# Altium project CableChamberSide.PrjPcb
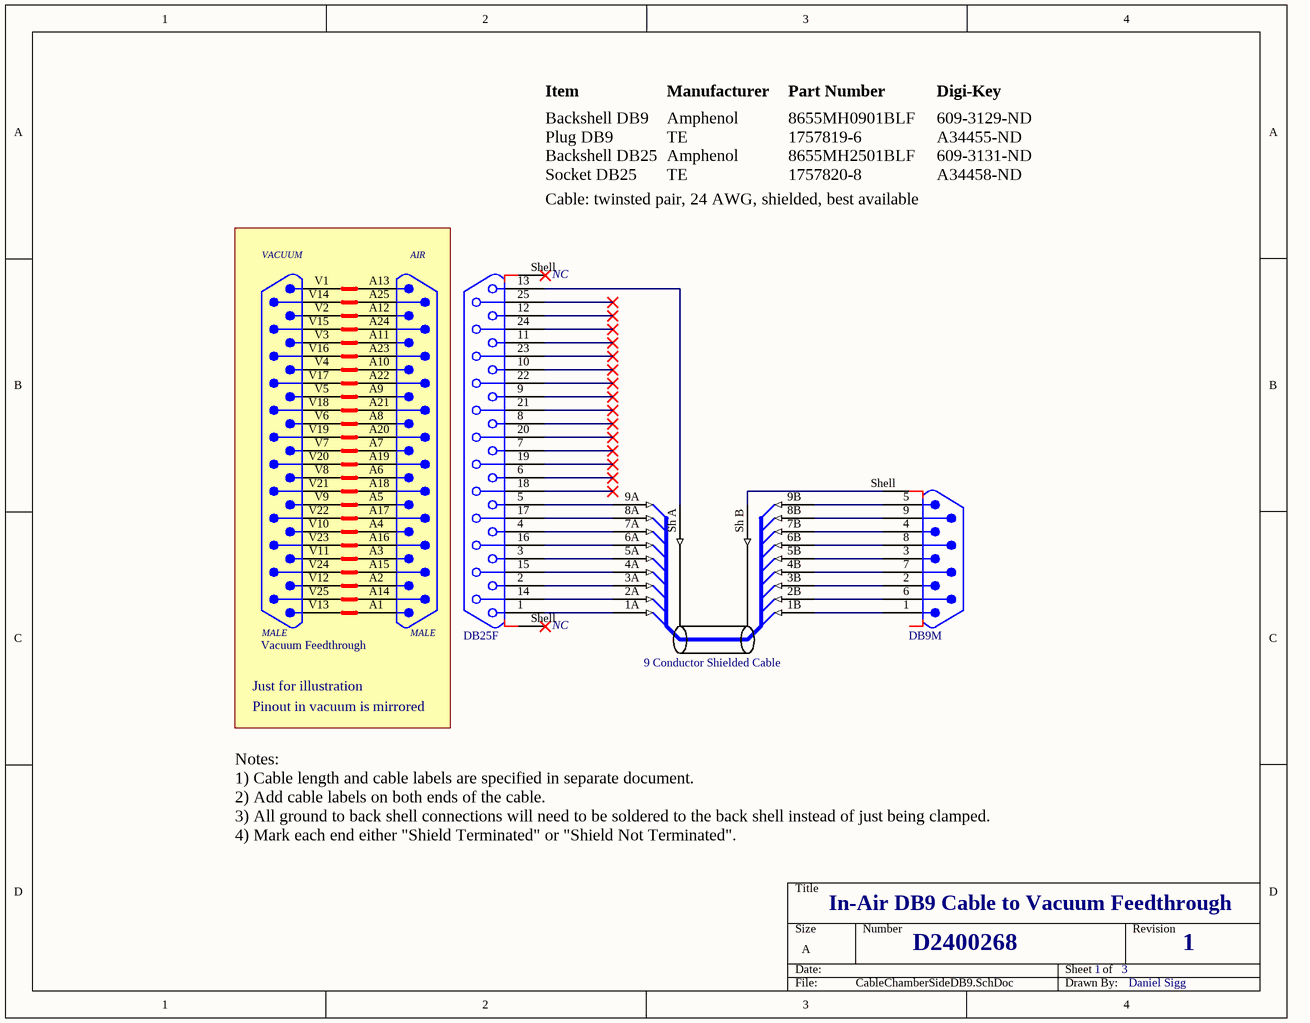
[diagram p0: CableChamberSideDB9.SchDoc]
Revision: 1; DCC: D2400268
3 sheets, 12 parts. Net scope: global (net labels, ports and power ports of the same name join across sheets).
Sheets:
  CableChamberSideDB9.SchDoc
  CableChamberSideDB15.SchDoc
  CableChamberSideDB25.SchDoc

## Sheet CableChamberSideDB9.SchDoc
size A; SheetNumber: 1; SheetTotal: 3

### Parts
Cable1  9 Conductor Shielded Cable
Feed1  Vacuum Feedthrough  (no BOM)
J1  DB25F
J2  DB9M  [DB9]

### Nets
NetCable1_1A: Cable1.1A J1.1
NetCable1_1B: Cable1.1B J2.1
NetCable1_2A: Cable1.2A J1.14
NetCable1_2B: Cable1.2B J2.6
NetCable1_3A: Cable1.3A J1.2
NetCable1_3B: Cable1.3B J2.2
NetCable1_4A: Cable1.4A J1.15
NetCable1_4B: Cable1.4B J2.7
NetCable1_5A: Cable1.5A J1.3
NetCable1_5B: Cable1.5B J2.3
NetCable1_6A: Cable1.6A J1.16
NetCable1_6B: Cable1.6B J2.8
NetCable1_7A: Cable1.7A J1.4
NetCable1_7B: Cable1.7B J2.4
NetCable1_8A: Cable1.8A J1.17
NetCable1_8B: Cable1.8B J2.9
NetCable1_9A: Cable1.9A J1.5
NetCable1_9B: Cable1.9B J2.5
NetCable1_Sh A: Cable1.Sh_A J1.13
NetCable1_Sh B: Cable1.Sh_B J2.Shell(SH1)

Not connected (* = marked no-connect by the designer): Feed1 A1 A2 A3 A4 A5 A6 A7 A8 A9 A10 A11 A12 A13 A14 A15 A16 A17 A18 A19 A20 A21 A22 A23 A24 A25 V1 V2 V3 V4 V5 V6 V7 V8 V9 V10 V11 V12 V13 V14 V15 V16 V17 V18 V19 V20 V21 V22 V23 V24 V25; J1 6* 7* 8* 9* 10* 11* 12* 18* 19* 20* 21* 22* 23* 24* 25* Shell*

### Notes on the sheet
- Item
- Manufacturer
- Part Number
- Digi-Key
- Backshell DB9
  Plug DB9
  Backshell DB25
  Socket DB25
- Cable: twinsted pair, 24 AWG, shielded, best available
- Amphenol
  TE
  Amphenol
  TE
- 8655MH0901BLF
  1757819-6
  8655MH2501BLF
  1757820-8
- 609-3129-ND
  A34455-ND
  609-3131-ND
  A34458-ND
- (near J1) NC
- Just for illustration
- Pinout in vacuum is mirrored
- Notes:
  1) Cable length and cable labels are specified in separate document.
  2) Add cable labels on both ends of the cable.
  3) All ground to back shell connections will need to be soldered to the back shell instead of just being clamped.
  4) Mark each end either "Shield Terminated" or "Shield Not Terminated".
- In-Air DB9 Cable to Vacuum Feedthrough
- Daniel Sigg

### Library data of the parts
Cable1 = Shielded 9 Cond: Connector A: 1757820-8; Connector B: 1757819-6
Feed1 = vac_feed_25p: Vacuum feedthrough 25-pin d-sub
J1 = D25-F-Shell: 25 Pin Female Cable End, D-Sub with Backshell
J2 = DB9M-Shell: 9 Pin Male Cable End, D-Sub with Backshell

## Sheet CableChamberSideDB15.SchDoc
size A; SheetNumber: 2; SheetTotal: 3
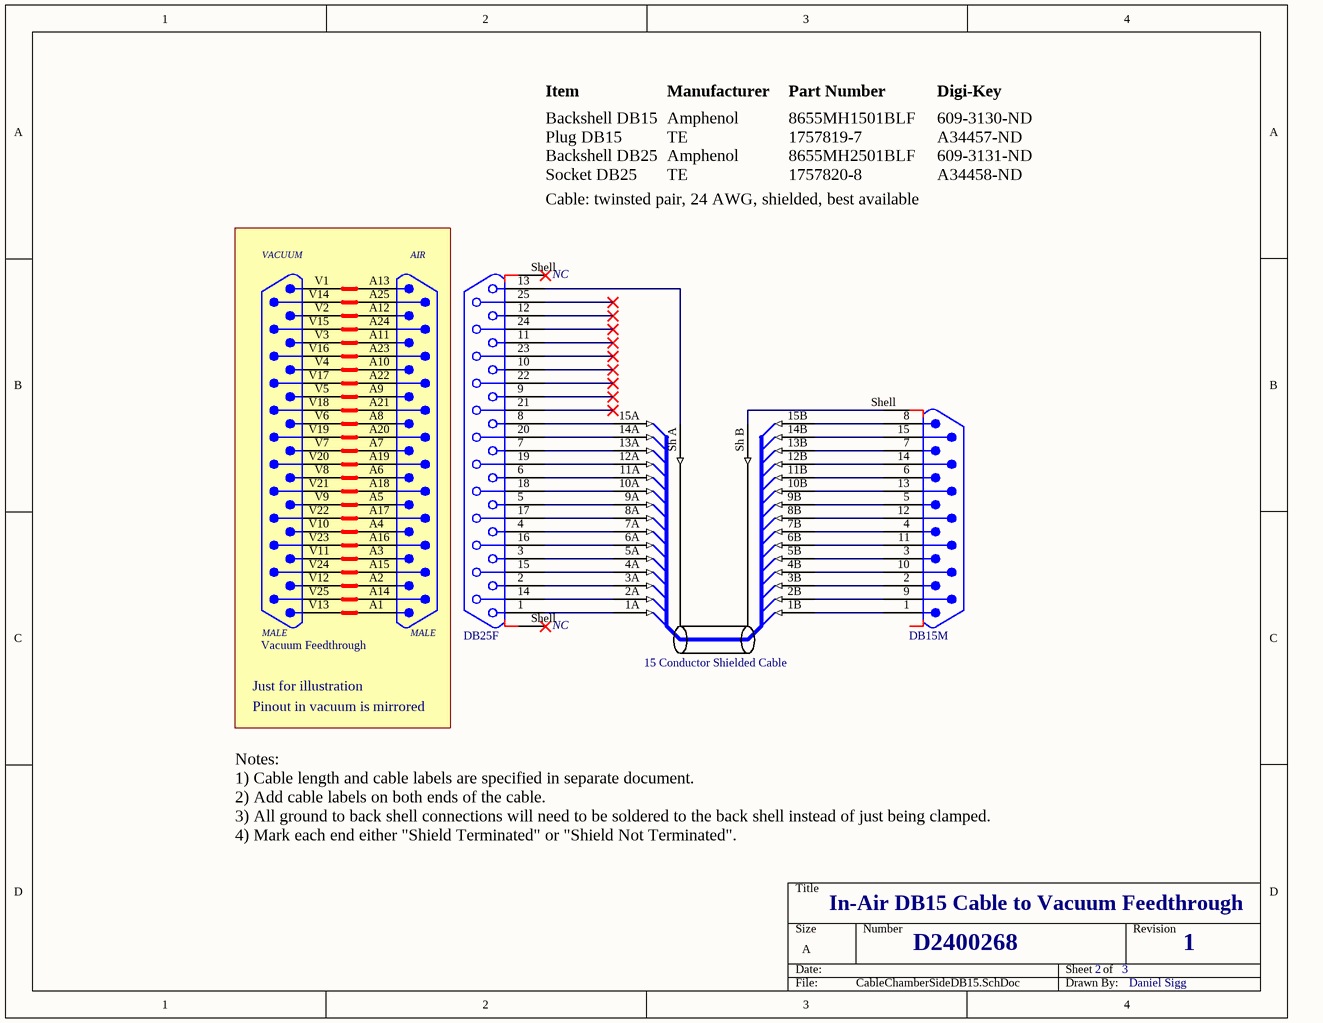
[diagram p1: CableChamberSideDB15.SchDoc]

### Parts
Cable2  15 Conductor Shielded Cable
Feed2  Vacuum Feedthrough  (no BOM)
J3  DB25F
J4  DB15M  [DB15]

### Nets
NetCable2_1A: Cable2.1A J3.1
NetCable2_1B: Cable2.1B J4.1
NetCable2_2A: Cable2.2A J3.14
NetCable2_2B: Cable2.2B J4.9
NetCable2_3A: Cable2.3A J3.2
NetCable2_3B: Cable2.3B J4.2
NetCable2_4A: Cable2.4A J3.15
NetCable2_4B: Cable2.4B J4.10
NetCable2_5A: Cable2.5A J3.3
NetCable2_5B: Cable2.5B J4.3
NetCable2_6A: Cable2.6A J3.16
NetCable2_6B: Cable2.6B J4.11
NetCable2_7A: Cable2.7A J3.4
NetCable2_7B: Cable2.7B J4.4
NetCable2_8A: Cable2.8A J3.17
NetCable2_8B: Cable2.8B J4.12
NetCable2_9A: Cable2.9A J3.5
NetCable2_9B: Cable2.9B J4.5
NetCable2_10A: Cable2.10A J3.18
NetCable2_10B: Cable2.10B J4.13
NetCable2_11A: Cable2.11A J3.6
NetCable2_11B: Cable2.11B J4.6
NetCable2_12A: Cable2.12A J3.19
NetCable2_12B: Cable2.12B J4.14
NetCable2_13A: Cable2.13A J3.7
NetCable2_13B: Cable2.13B J4.7
NetCable2_14A: Cable2.14A J3.20
NetCable2_14B: Cable2.14B J4.15
NetCable2_15A: Cable2.15A J3.8
NetCable2_15B: Cable2.15B J4.8
NetCable2_Sh A: Cable2.Sh_A J3.13
NetCable2_Sh B: Cable2.Sh_B J4.Shell(SH1)

Not connected (* = marked no-connect by the designer): Feed2 A1 A2 A3 A4 A5 A6 A7 A8 A9 A10 A11 A12 A13 A14 A15 A16 A17 A18 A19 A20 A21 A22 A23 A24 A25 V1 V2 V3 V4 V5 V6 V7 V8 V9 V10 V11 V12 V13 V14 V15 V16 V17 V18 V19 V20 V21 V22 V23 V24 V25; J3 9* 10* 11* 12* 21* 22* 23* 24* 25* Shell*

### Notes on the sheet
- Item
- Manufacturer
- Part Number
- Digi-Key
- Backshell DB15
  Plug DB15
  Backshell DB25
  Socket DB25
- Cable: twinsted pair, 24 AWG, shielded, best available
- Amphenol
  TE
  Amphenol
  TE
- 8655MH1501BLF
  1757819-7
  8655MH2501BLF
  1757820-8
- 609-3130-ND
  A34457-ND
  609-3131-ND
  A34458-ND
- (near J3) NC
- Just for illustration
- Pinout in vacuum is mirrored
- Notes:
  1) Cable length and cable labels are specified in separate document.
  2) Add cable labels on both ends of the cable.
  3) All ground to back shell connections will need to be soldered to the back shell instead of just being clamped.
  4) Mark each end either "Shield Terminated" or "Shield Not Terminated".
- In-Air DB15 Cable to Vacuum Feedthrough
- Daniel Sigg

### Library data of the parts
Cable2 = Shielded 15 Cond: Connector A: 1757820-8; Connector B: 1757819-7
Feed2 = vac_feed_25p: Vacuum feedthrough 25-pin d-sub
J3 = D25-F-Shell: as J1 on sheet CableChamberSideDB9
J4 = DB15M-Shell: 15 Pin Male Cable End, D-Sub with Backshell

## Sheet CableChamberSideDB25.SchDoc
size A; SheetNumber: 3; SheetTotal: 3
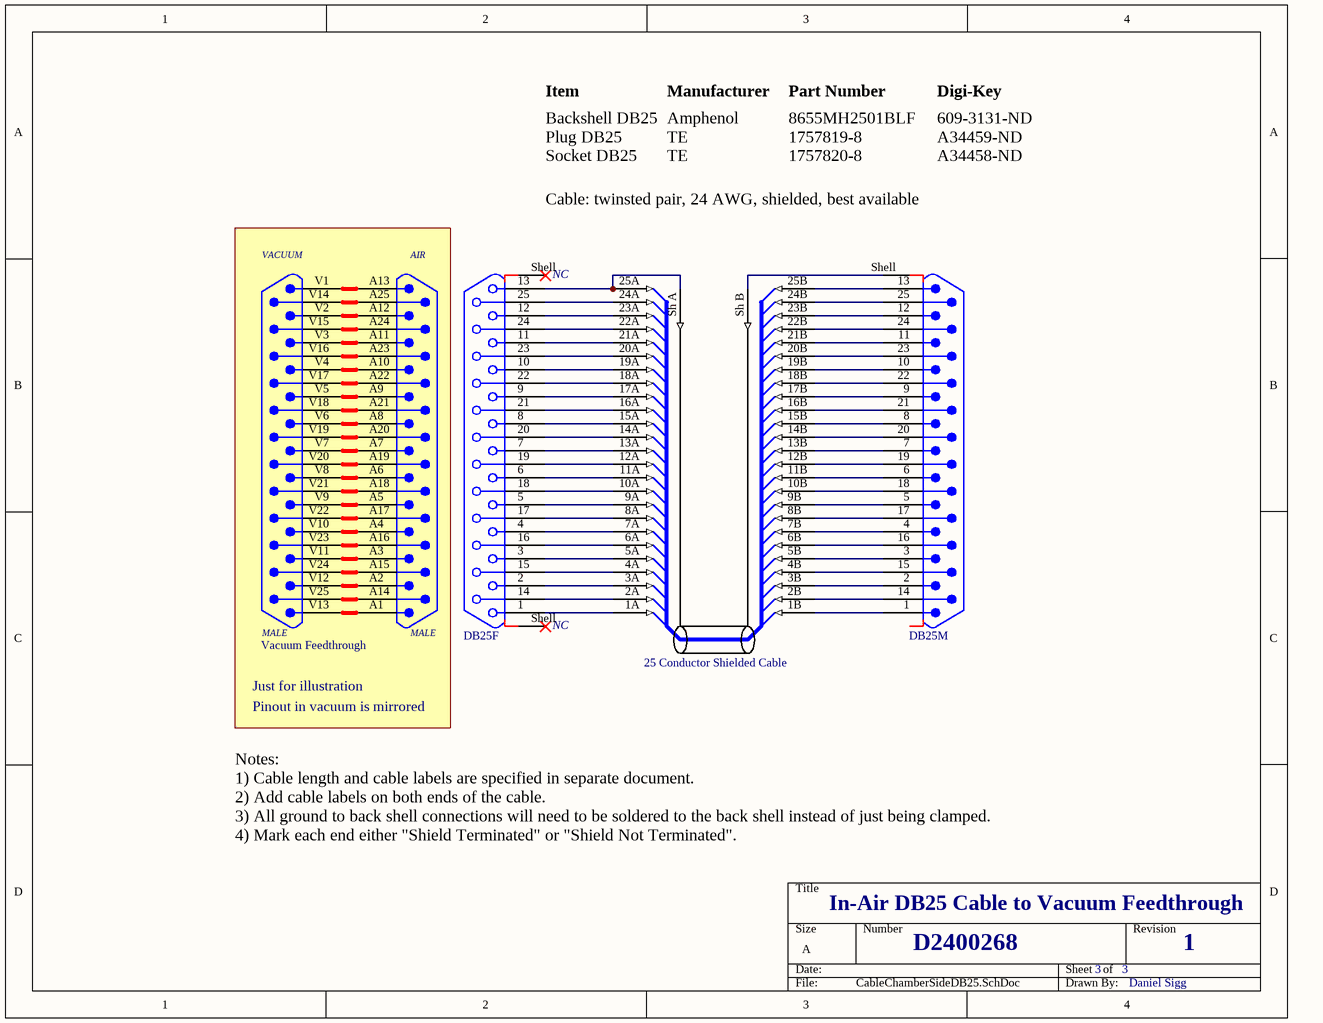
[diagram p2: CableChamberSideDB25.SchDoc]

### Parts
Cable3  25 Conductor Shielded Cable
Feed3  Vacuum Feedthrough  (no BOM)
J5  DB25M
J6  DB25F

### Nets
NetCable3_1A: Cable3.1A J6.1
NetCable3_1B: Cable3.1B J5.1
NetCable3_2A: Cable3.2A J6.14
NetCable3_2B: Cable3.2B J5.14
NetCable3_3A: Cable3.3A J6.2
NetCable3_3B: Cable3.3B J5.2
NetCable3_4A: Cable3.4A J6.15
NetCable3_4B: Cable3.4B J5.15
NetCable3_5A: Cable3.5A J6.3
NetCable3_5B: Cable3.5B J5.3
NetCable3_6A: Cable3.6A J6.16
NetCable3_6B: Cable3.6B J5.16
NetCable3_7A: Cable3.7A J6.4
NetCable3_7B: Cable3.7B J5.4
NetCable3_8A: Cable3.8A J6.17
NetCable3_8B: Cable3.8B J5.17
NetCable3_9A: Cable3.9A J6.5
NetCable3_9B: Cable3.9B J5.5
NetCable3_10A: Cable3.10A J6.18
NetCable3_10B: Cable3.10B J5.18
NetCable3_11A: Cable3.11A J6.6
NetCable3_11B: Cable3.11B J5.6
NetCable3_12A: Cable3.12A J6.19
NetCable3_12B: Cable3.12B J5.19
NetCable3_13A: Cable3.13A J6.7
NetCable3_13B: Cable3.13B J5.7
NetCable3_14A: Cable3.14A J6.20
NetCable3_14B: Cable3.14B J5.20
NetCable3_15A: Cable3.15A J6.8
NetCable3_15B: Cable3.15B J5.8
NetCable3_16A: Cable3.16A J6.21
NetCable3_16B: Cable3.16B J5.21
NetCable3_17A: Cable3.17A J6.9
NetCable3_17B: Cable3.17B J5.9
NetCable3_18A: Cable3.18A J6.22
NetCable3_18B: Cable3.18B J5.22
NetCable3_19A: Cable3.19A J6.10
NetCable3_19B: Cable3.19B J5.10
NetCable3_20A: Cable3.20A J6.23
NetCable3_20B: Cable3.20B J5.23
NetCable3_21A: Cable3.21A J6.11
NetCable3_21B: Cable3.21B J5.11
NetCable3_22A: Cable3.22A J6.24
NetCable3_22B: Cable3.22B J5.24
NetCable3_23A: Cable3.23A J6.12
NetCable3_23B: Cable3.23B J5.12
NetCable3_24A: Cable3.24A J6.25
NetCable3_24B: Cable3.24B J5.25
NetCable3_25A: Cable3.25A Cable3.Sh_A J6.13
NetCable3_25B: Cable3.25B J5.13
NetCable3_Sh B: Cable3.Sh_B J5.Shell(SH1)

Not connected (* = marked no-connect by the designer): Feed3 A1 A2 A3 A4 A5 A6 A7 A8 A9 A10 A11 A12 A13 A14 A15 A16 A17 A18 A19 A20 A21 A22 A23 A24 A25 V1 V2 V3 V4 V5 V6 V7 V8 V9 V10 V11 V12 V13 V14 V15 V16 V17 V18 V19 V20 V21 V22 V23 V24 V25; J6 Shell*

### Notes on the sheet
- Item
- Manufacturer
- Part Number
- Digi-Key
- Backshell DB25
  Plug DB25
  Socket DB25
- Cable: twinsted pair, 24 AWG, shielded, best available
- Amphenol
  TE
  TE
- 8655MH2501BLF
  1757819-8
  1757820-8
- 609-3131-ND
  A34459-ND
  A34458-ND
- (near J6) NC
- Just for illustration
- Pinout in vacuum is mirrored
- Notes:
  1) Cable length and cable labels are specified in separate document.
  2) Add cable labels on both ends of the cable.
  3) All ground to back shell connections will need to be soldered to the back shell instead of just being clamped.
  4) Mark each end either "Shield Terminated" or "Shield Not Terminated".
- In-Air DB25 Cable to Vacuum Feedthrough
- Daniel Sigg

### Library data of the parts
Cable3 = Shielded 25 Cond: Connector A: 1757820-8; Connector B: 1757819-8
Feed3 = vac_feed_25p: Vacuum feedthrough 25-pin d-sub
J5 = D25M-Shell: 25 Pin Male Cable End, D-Sub with Backshell
J6 = D25-F-Shell: as J1 on sheet CableChamberSideDB9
